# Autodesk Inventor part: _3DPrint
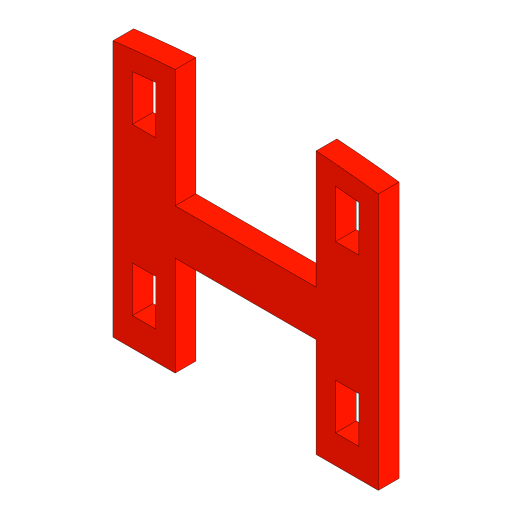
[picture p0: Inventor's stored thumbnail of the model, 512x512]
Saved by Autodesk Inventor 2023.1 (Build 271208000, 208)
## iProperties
Created: 2021-02
Part Number: _3DPrint
Material: Generic
Document SubType Name: Modeling
Designer: ftrauzettel
Density: 1 g/cm^3
Appearance: Default
Author: ftrauzettel
Part Number: multipartHbeam
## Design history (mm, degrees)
sketch "Sketch1"
  geometry: L1 (1.5, 19)-(-1.5, 19); L2 (-1.5, 19)-(-1.5, 20.5); L3 (-1.5, 20.5)-(1.5, 20.5); L4 (1.5, 20.5)-(1.5, 19); L5 (1.5, 19)-(-1.5, 20.5); L6 (-1.5, 19)-(1.5, 20.5); L7 (1.5, 21.995)-(-1.5, 21.995); L8 (-1.5, 21.995)-(-1.5, 23.495); L9 (-1.5, 23.495)-(1.5, 23.495); L10 (1.5, 23.495)-(1.5, 21.995); L11 (1.5, 21.995)-(-1.5, 23.495); L12 (-1.5, 21.995)-(1.5, 23.495); L13 (-1.7, 21.795)-(1.7, 21.795); L14 (1.7, 21.795)-(1.7, 23.695); L15 (1.7, 23.695)-(1.7, 23.695); L16 (-1.7, 23.695)-(-1.7, 21.795); L17 (-1.7, 18.8)-(1.7, 18.8); L18 (1.7, 18.8)-(1.7, 20.7); L19 (1.7, 20.7)-(-1.7, 20.7); L20 (-1.7, 20.7)-(-1.7, 18.8); L21 (-3.2, 24.492)-(-3.2, 18.018); L22 (3.2, 24.492)-(3.2, 18.018); L23 (-1.7, 23.695)-(-1.7, 24.641); L24 (1.7, 23.695)-(1.7, 24.641); L25 (-1.7, 23.695)-(-1.7, 23.695); L26 (1.7, 23.695)-(-1.7, 23.695); L27 (-3.2, 18.3)-(-1.7, 18.3); L28 (-1.7, 18.8)-(-1.7, 18.221); L29 (1.7, 18.8)-(1.7, 18.221); L30 (-1.7, 18.3)-(1.7, 18.3); L31 (1.7, 18.3)-(3.2, 18.3); C1 r 18 at (0, 0); C2 r 25 at (0, 0); A1 r 24.7 centre (0, 0) between (-3.2, 24.492) and (3.2, 24.492); A2 r 18.3 centre (0, 0) between (-3.2, 18.018) and (3.2, 18.018); 5 further points
  constraints: 62 end point, 12 parallel, 9 perpendicular, 8 point on circle, 6 midpoint, 6 point on line, 4 centre point, 3 tangent, 2 coincident, 2 horizontal, 2 vertical, 2 vertical alignment, 4 other
  dimensions: "d2" = 36 diameter of C1; "d3" = 50 diameter of C2; "d4" = 0.3 radial gap between concentric circles of C2 A1; "d5" = 0.3 radial gap between concentric circles of C1 A2; "d6" = 3 distance of L2.end L3.end; "d7" = 1.5 distance of L1.end L2.end; "d8" = 20.5 distance from line of point (0, 0) L3; "d9" = 21.995 distance from line of C1.centre L7; "d10" = 3 distance of L7.start L7.end; "d11" = 1.5 distance of L7.end L8.end (= d7); "d12" = 0.2 distance between parallel lines of L7 L13; "d13" = 0.2 distance between parallel lines of L1 L17 (= d12); "d14" = 1.5 distance between parallel lines of L16 L21; "d15" = 1.5 distance between parallel lines of L22 L18 (= d14); "d16" = 1.7 distance from line of point (0, 22.745) L23 (computed from d12); "d17" = 1.7 distance from line of point (0, 22.745) L24 (= d16); "d18" = 0.2 distance between parallel lines of L16 L8 (= d12); "d19" = 0.2 distance between parallel lines of L25 L9 (= d12); "d20" = 3.4 distance between parallel lines of L29 L28 (computed from d12); "d21" = 1.7 distance from line of point (0, 19.75) L28 (= 0.5 x d20)
extrude "Extrusion1" new body sketch "Sketch1" distance "d22" = 0.5; taper "d23" = 0 deg
sketch "Sketch5"
  geometry: L1 (-2.45, 23.828)-(-2.45, 19.268); L2 (-2.732, 24.08)-(-2.732, 18.986); L3 (-2.168, 18.986)-(-2.168, 24.137); L4 (-3.2, 18.3)-(-1.7, 18.3) reference; L5 (-1.7, 18.3)-(-1.7, 20.7) reference; L6 (-2.732, 18.986)-(-2.168, 18.986); L7 (-3.2, 24.492)-(-3.2, 18.3) reference; L8 (-2.732, 22.98)-(-2.168, 22.98); L9 (-2.168, 20.086)-(-2.732, 20.086); A1 r 0.282 centre (-2.45, 23.828) between (-2.168, 23.828) and (-2.732, 23.828); A2 r 0.282 centre (-2.45, 19.268) between (-2.732, 19.268) and (-2.168, 19.268); A3 r 24.7 centre (0, 0) between (-1.7, 24.641) and (-3.2, 24.492) reference; A4 r 24.234 centre (0, 0) between (-1.557, 24.184) and (-3.017, 24.046); 6 further points
  constraints: 14 end point, 12 point on circle, 8 point on line, 4 tangent, 3 centre point, 3 midpoint, 2 perpendicular, 1 horizontal, 1 parallel, 1 vertical
  dimensions: "d46" = 0.68562 distance from line of point (-2.45, 18.986) L4 (= wall3); "d47" = 0.46781 distance of point (-2.451, 24.578) point (-2.45, 24.11) (= wall2); "d51" = 0.46781 distance from line of point (-1.7, 19.5) L3 (= wall2); "d52" = 0.46781 distance between parallel lines of L7 L2 (= wall2); "d53" = 1.1 distance from line of L2.start L8; "d54" = 1.1 distance between parallel lines of L6 L9 (= d53)
extrude "Extrusion5" cut sketch "Sketch5" extent not by distance; stored distance "d49" = 0; taper "d50" = 0 deg
mirror "Mirror1"
sketch "Sketch2"
  geometry: C1 r 0.5 at (1.7, 0); 1 further point
  constraints: 1 centre point, 1 coincident
  dimensions: "d24" = 1 diameter of C1
extrude "Extrusion2" join sketch "Sketch2" stored distance "d25" = 0.5; taper "d26" = 0 deg
sketch "Sketch3"
  geometry: L1 (-1.6, 20.6)-(1.6, 20.6) reference; C1 r 0.3 at (0, 21.247); 1 further point
  constraints: 1 centre point, 1 vertical alignment
  dimensions: "d27" = 0.6 diameter of C1; "d28" = 0.6475 distance from line of L1 C1.centre
extrude "Extrusion3" cut sketch "Sketch3" extent not by distance; stored distance "d29" = 0; taper "d30" = 0 deg
sketch "Sketch4"
  geometry: L1 (-3.2, 24.492)-(-3.2, 18.3) reference; L2 (-1.6, 23.595)-(-0.6, 23.595) reference; L3 (3.2, 18.3)-(3.2, 24.492) reference; L4 (0.6, 23.595)-(1.6, 23.595) reference; L5 (-3.2, 18.3)-(-1.7, 18.3) reference; L6 (1.7, 18.3)-(3.2, 18.3) reference; C1 r 0.3 at (-3.7, 24.244); C2 r 0.3 at (3.7, 24.244); C3 r 0.3 at (-3.7, 18.833); C4 r 0.3 at (3.7, 18.833); 1 further point
  constraints: 4 centre point
  dimensions: "d31" = 0.6 diameter of C1; "d32" = 0.5 distance from line of L1 C1.centre; "d33" = 0.649 distance from line of L2 C1.centre; "d34" = 0.6 diameter of C2; "d35" = 0.5 distance from line of L3 C2.centre; "d36" = 0.649 distance from line of C2.centre L4 (= d33); "d37" = 0.6 diameter of C3; "d38" = 0.5 distance from line of L1 C3.centre (= d32); "d39" = 0.53333 distance from line of C3.centre L5; "d40" = 0.6 diameter of C4; "d41" = 0.5 distance from line of L3 C4.centre; "d42" = 0.53333 distance from line of L6 C4.centre (= d39)
extrude "Extrusion4" cut sketch "Sketch4" extent not by distance; stored distance "d43" = 0; taper "d44" = 0 deg
body "Solid1"
other parameters: "layerHeight" = 0.15 [user parameter; used in 1 equation term], "extrusionWidth" = 0.25 [user parameter; used in 4 equation terms], "extrusionSpacing" = 0.21781 (= extrusionWidth - 0.214602 x layerHeight) [user parameter; used in 3 equation terms], "wall1" = 0.25 (= 0 x extrusionSpacing + extrusionWidth) [user parameter], "wall2" = 0.46781 (= extrusionSpacing + extrusionWidth) [user parameter; used in 3 equation terms], "wall3" = 0.68562 (= 2 x extrusionSpacing + extrusionWidth) [user parameter; used in 1 equation term]
